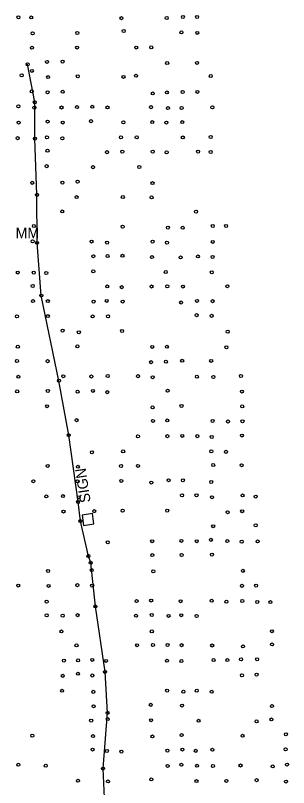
# Model space of a CAD drawing. Extents: x 20503438 to 20508873, y 7964251 to 7984667.
# Drawn here: x 20506775 to 20506955, y 7973633 to 7974141 of the extents above; entities that cross this region are included whole.
import ezdxf

# ---------------------------------------------------------------- set-up
doc = ezdxf.new("R2010")
doc.units = 0
for name, color, linetype in [('SurDrainageArrowUp', 7, 'Continuous'), ('SurPointsNonDTM', 7, 'Continuous'), ('SurRoadPoints', 7, 'Continuous'), ('SurSurveyPoints', 7, 'Continuous')]:
    doc.layers.add(name, color=color, linetype=linetype)

msp = doc.modelspace()

# ---------------------------------------------------------------- linework, layer by layer
at = {"layer": 'SurDrainageArrowUp'}
msp.add_lwpolyline([(20506852.02, 7973571.65), (20506842.01, 7973570.52), (20506833.7, 7973578.57), (20506836.87, 7973598.21), (20506833.39, 7973626.05), (20506832.49, 7973645.33), (20506835.48, 7973682), (20506833.81, 7973708.94), (20506827.5, 7973752.01), (20506824.39, 7973780.77), (20506822.88, 7973785.18), (20506817.64, 7973808.18), (20506816.09, 7973820.75), (20506809.95, 7973864.68), (20506803.46, 7973900.57), (20506791.8, 7973956.59), (20506789.08, 7973991.29), (20506788.95, 7974022.89), (20506787.58, 7974059.9), (20506787.54, 7974083.77), (20506782.83, 7974108.81)], dxfattribs=at)
at = {"layer": 'SurPointsNonDTM'}
for centre in [(20506778.89, 7974101.58), (20506785.63, 7974104.45)]:
    msp.add_circle(centre, 1, dxfattribs=at)
at = {"layer": 'SurRoadPoints'}
msp.add_lwpolyline([(20506825.99, 7973809.76), (20506825.99, 7973809.76), (20506825.48, 7973813.15), (20506818.7, 7973812.13), (20506819.72, 7973805.35), (20506826.5, 7973806.37), (20506825.99, 7973809.76)], dxfattribs=at)
at = {"layer": 'SurSurveyPoints'}
for centre in [(20506776.78, 7974139.73), (20506785.19, 7974139.64), (20506844.63, 7974139.15), (20506874.48, 7974139.26), (20506885.14, 7974139.95), (20506894.5, 7974139.95), (20506786.11, 7974129.2), (20506815.56, 7974129.4), (20506846.13, 7974130.75), (20506884.16, 7974129.83), (20506894.57, 7974129.46), (20506785.67, 7974119.65), (20506815.43, 7974119.84), (20506854.35, 7974119.82), (20506864.26, 7974119.96), (20506782.83, 7974108.81), (20506795.6, 7974110.37), (20506805.81, 7974110.54), (20506874.77, 7974109.62), (20506894.46, 7974109.73), (20506815.87, 7974100.9), (20506845.98, 7974100.51), (20506854.25, 7974101.25), (20506903.51, 7974101.05), (20506796.33, 7974100.37), (20506785.57, 7974090.98), (20506795.93, 7974090.39), (20506805.92, 7974090.73), (20506884.94, 7974090.61), (20506894.73, 7974090.65), (20506865.26, 7974089.6), (20506874.57, 7974090.28), (20506776.7, 7974081.17), (20506787.28, 7974080.28), (20506787.54, 7974083.77), (20506805.14, 7974080.37), (20506815.37, 7974080.63), (20506825.38, 7974080.85), (20506835.45, 7974080.42), (20506864.1, 7974080.58), (20506904.55, 7974080.5), (20506875.28, 7974079.96), (20506884.29, 7974080.02), (20506776.89, 7974070.48), (20506795.98, 7974071.13), (20506805.96, 7974070.47), (20506824.61, 7974071.37), (20506845.92, 7974070.63), (20506864.91, 7974070.75), (20506874.25, 7974070.47), (20506884.71, 7974070.76), (20506776.22, 7974060.19), (20506787.58, 7974059.9), (20506795.55, 7974060.75), (20506805.69, 7974060.09), (20506844.31, 7974060.71), (20506854.69, 7974060.7), (20506885.08, 7974060.68), (20506903.47, 7974061), (20506795.91, 7974051.94), (20506835.08, 7974050.97), (20506845.19, 7974051.32), (20506865.22, 7974051.32), (20506874.42, 7974050.85), (20506895.17, 7974051.33), (20506903.47, 7974051.12), (20506795.35, 7974041.75), (20506825.89, 7974041.1), (20506856.42, 7974041.22), (20506785.86, 7974030.8), (20506805.76, 7974030.91), (20506815.78, 7974031.58), (20506865.11, 7974030.59), (20506788.95, 7974022.89), (20506815.05, 7974021.4), (20506845.55, 7974021.46), (20506864.46, 7974021.2), (20506805.63, 7974011.95), (20506893.79, 7974011.85), (20506786.95, 7974002.35), (20506845.44, 7974001.98), (20506875.24, 7974001.32), (20506885, 7974001.23), (20506904.84, 7974002.42), (20506913.62, 7974002.4), (20506786.1, 7973992.31), (20506789.08, 7973991.29), (20506824.92, 7973992.13), (20506835.18, 7973991.42), (20506865.13, 7973992.12), (20506874.61, 7973991.42), (20506904.8, 7973991.91), (20506826.13, 7973982.49), (20506835.46, 7973982.6), (20506845.32, 7973982.79), (20506864.75, 7973981.9), (20506883.62, 7973981.69), (20506895.03, 7973982.35), (20506904.65, 7973981.99), (20506776.32, 7973971.76), (20506786.89, 7973971.69), (20506795.11, 7973971.5), (20506826.1, 7973972.51), (20506873.87, 7973972.09), (20506904.18, 7973971.94), (20506786.16, 7973962.92), (20506835.24, 7973962.6), (20506844.85, 7973962.12), (20506864.46, 7973962.57), (20506874.86, 7973962.7), (20506885.11, 7973962.54), (20506914.42, 7973962.76), (20506791.8, 7973956.59), (20506786.34, 7973952.96), (20506796.12, 7973952.94), (20506826.26, 7973952.61), (20506834.95, 7973953.12), (20506845.48, 7973952.64), (20506883.94, 7973952.03), (20506894.45, 7973953.11), (20506904.66, 7973952.92), (20506796.12, 7973943.1), (20506835.79, 7973942.97), (20506894.16, 7973943.69), (20506904.04, 7973943.26), (20506775.81, 7973942.96), (20506825.64, 7973942.88), (20506805.82, 7973933.51), (20506845.08, 7973933.32), (20506914.64, 7973932.82), (20506816.55, 7973932.45), (20506776.35, 7973922.95), (20506815.64, 7973923.19), (20506864.93, 7973922.84), (20506874.56, 7973922.89), (20506913.82, 7973922.58), (20506775.77, 7973913.5), (20506796.01, 7973913.44), (20506864.2, 7973912.77), (20506873.9, 7973913.06), (20506884.64, 7973913.67), (20506903.75, 7973913.61), (20506776.76, 7973903.16), (20506806.31, 7973903.54), (20506824.83, 7973903.34), (20506835.59, 7973903.62), (20506855.52, 7973903.56), (20506865.21, 7973902.87), (20506894.35, 7973903.19), (20506905.21, 7973903.05), (20506923.38, 7973903.67), (20506803.46, 7973900.57), (20506775.92, 7973893.53), (20506796.12, 7973893.8), (20506815.69, 7973893.35), (20506825.81, 7973893.88), (20506835.27, 7973893.04), (20506875.05, 7973893.92), (20506924, 7973893.41), (20506795.63, 7973883.77), (20506865.14, 7973883.03), (20506884.21, 7973883.94), (20506924.23, 7973883.68), (20506815.05, 7973874.59), (20506865.41, 7973874.12), (20506874.8, 7973874.4), (20506904.69, 7973874.1), (20506914.88, 7973873.73), (20506924.4, 7973873.87), (20506809.95, 7973864.68), (20506855.51, 7973863.94), (20506874.88, 7973864.07), (20506884.68, 7973864.26), (20506894.61, 7973864.08), (20506904.16, 7973863.53), (20506924.01, 7973864.46), (20506825.14, 7973853.46), (20506845.77, 7973854.05), (20506903.86, 7973854.14), (20506913.58, 7973853.77), (20506796.03, 7973844.53), (20506815.93, 7973843.93), (20506844.36, 7973844.45), (20506855.52, 7973844.5), (20506905.13, 7973845.09), (20506923.85, 7973844.95), (20506786.58, 7973834.44), (20506815.75, 7973834.35), (20506844.52, 7973834.63), (20506864.33, 7973833.55), (20506875.73, 7973835.07), (20506885.11, 7973835.04), (20506903.79, 7973833.95), (20506795.13, 7973824.39), (20506806.03, 7973824.64), (20506816.51, 7973823.91), (20506884.54, 7973825.15), (20506894.09, 7973825.18), (20506904.3, 7973823.89), (20506924.45, 7973825.04), (20506933.12, 7973824.33), (20506816.09, 7973820.75), (20506806.45, 7973814.44), (20506826.69, 7973814.71), (20506845.43, 7973815.04), (20506874.8, 7973815.08), (20506914.61, 7973814.03), (20506924.19, 7973814.7), (20506817.64, 7973808.18), (20506905.08, 7973804.82), (20506933.1, 7973805.43), (20506903.58, 7973795.85), (20506835.61, 7973794.23), (20506864.88, 7973794.94), (20506884.19, 7973795.16), (20506894.29, 7973794.92), (20506914.38, 7973795.02), (20506923.89, 7973794.63), (20506934.37, 7973794.81), (20506864.96, 7973785.8), (20506884.31, 7973785.87), (20506904.24, 7973786.09), (20506822.88, 7973785.18), (20506824.39, 7973780.77), (20506796.29, 7973775.37), (20506825.09, 7973775.94), (20506924.67, 7973775.46), (20506865.64, 7973775.12), (20506776.62, 7973765.74), (20506796.59, 7973765.56), (20506815.58, 7973766.01), (20506825.34, 7973765.7), (20506924.11, 7973765.57), (20506933.37, 7973765.71), (20506795.34, 7973755.2), (20506854.62, 7973755.53), (20506864.22, 7973755.87), (20506883.61, 7973755.45), (20506904.13, 7973755.76), (20506913.84, 7973755.15), (20506924.26, 7973755.57), (20506827.5, 7973752.01), (20506934.09, 7973754.95), (20506942.82, 7973754.85), (20506795.4, 7973746.2), (20506805.94, 7973745.9), (20506815.72, 7973746.27), (20506854.23, 7973745.87), (20506864.6, 7973746.42), (20506875.68, 7973745.78), (20506884.03, 7973746.24), (20506894.18, 7973745.73), (20506805.12, 7973735.56), (20506864.66, 7973735.6), (20506943.78, 7973735.71), (20506815.02, 7973726.4), (20506854.94, 7973726.47), (20506865.4, 7973726.63), (20506875.01, 7973726.65), (20506884.23, 7973726.54), (20506904.42, 7973726.32), (20506924.71, 7973725.67), (20506943.86, 7973727.02), (20506806.73, 7973716.34), (20506816.08, 7973716.53), (20506825.37, 7973716.84), (20506834.51, 7973716.2), (20506874.62, 7973716.26), (20506884.15, 7973716.11), (20506905.32, 7973716.73), (20506914.37, 7973716.68), (20506923.42, 7973717.2), (20506934.02, 7973717.21), (20506806, 7973706.36), (20506815.95, 7973707.71), (20506825.44, 7973706.56), (20506833.81, 7973708.94), (20506924.03, 7973706.71), (20506933.67, 7973707.15), (20506805.55, 7973696.51), (20506826.09, 7973695.81), (20506874.73, 7973696.62), (20506885.5, 7973695.92), (20506894.27, 7973696.58), (20506904.12, 7973695.87), (20506826.32, 7973686.36), (20506863.97, 7973687.27), (20506884.58, 7973686.81), (20506943.83, 7973686.44), (20506835.48, 7973682), (20506824.69, 7973676.88), (20506835.65, 7973677.89), (20506864.17, 7973677.16), (20506895.44, 7973676.79), (20506933.67, 7973676.38), (20506943.48, 7973677.64), (20506785.9, 7973666.93), (20506825.92, 7973666.69), (20506865.06, 7973666.47), (20506884.29, 7973667.35), (20506924.44, 7973666.89), (20506952.98, 7973667.85), (20506825.59, 7973657.82), (20506835.06, 7973656.91), (20506844.66, 7973656.49), (20506874.93, 7973657.11), (20506884.82, 7973657.84), (20506893.6, 7973656.98), (20506904.53, 7973657.7), (20506952.81, 7973658.02), (20506776.66, 7973647.82), (20506794.76, 7973647.2), (20506832.49, 7973645.33), (20506875.08, 7973647.07), (20506884.11, 7973647.82), (20506894.51, 7973647.18), (20506904.96, 7973647.01), (20506923.09, 7973647.35), (20506944.29, 7973646.7), (20506953.77, 7973647.97), (20506864.31, 7973638.17), (20506815.98, 7973637.29), (20506835.79, 7973636.83), (20506894.09, 7973637.05), (20506913.8, 7973637.2), (20506933.73, 7973637.68), (20506953.1, 7973636.76)]:
    msp.add_circle(centre, 1, dxfattribs=at)

# ---------------------------------------------------------------- texts
at = {"layer": 'SurRoadPoints'}
for s, rotation, p in [('MM', 360, (20506774.87, 7973994.34)), ('SIGN', 98.5563, (20506824.39, 7973820.86))]:
    msp.add_text(s, height=6.995, rotation=rotation, dxfattribs=at).set_placement(p)

doc.saveas('drawing.dxf')
